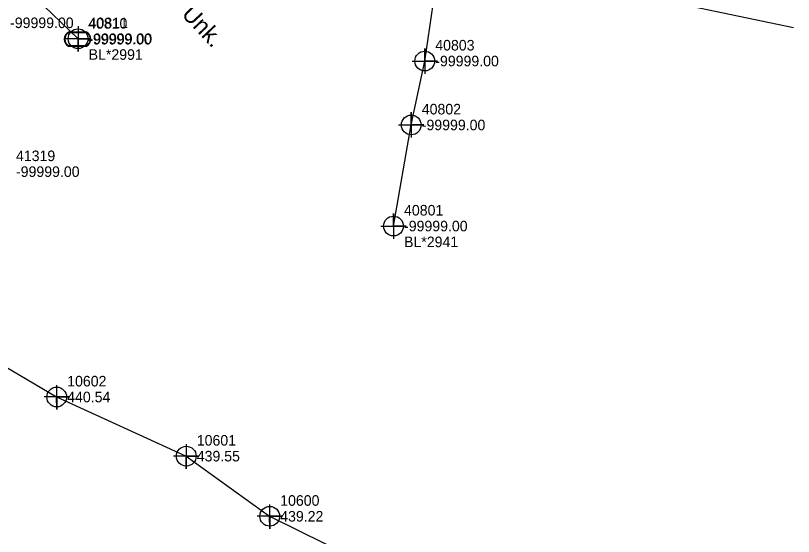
# Model space of a CAD drawing. Extents: x 2083698 to 2094313, y 743246 to 752873.
# Drawn here: x 2091601.9 to 2091786.2, y 744139.8 to 744263.2 of the extents above; entities that cross this region are included whole.
import ezdxf

# ---------------------------------------------------------------- set-up
doc = ezdxf.new("R2010")
doc.units = 0
for name, color, linetype in [('COGO Default Chain', 7, 'Continuous'), ('COGO Default Curve', 7, 'Continuous'), ('COGO Default Point Number', 7, 'Continuous'), ('Default Symbol Cogo Comment', 7, 'Continuous'), ('Exist Guardrail', 7, 'Continuous'), ('Exist Property Line', 7, 'Continuous'), ('Exist Right of Way Easement Line', 7, 'Continuous'), ('Exist Right of Way Line', 7, 'Continuous'), ('Exist Right of Way Line Leader', 7, 'Continuous'), ('Exist Right of Way Line Text', 7, 'Continuous'), ('Exist Right of Way Width CELL', 7, 'Continuous'), ('Exist Utilities Gas UG Line SUE LOS B', 7, 'Continuous'), ('Exist Utilities Other Pole CELL', 7, 'Continuous'), ('Exist Utilities Power Joint Use Telephone Cogo Elevation', 7, 'Continuous'), ('Exist Utilities Power Joint Use Telephone Cogo Number', 7, 'Continuous'), ('Exist Utilities Telephone UG Conduit SUE LOS B', 7, 'Continuous'), ('Exist Utilities TV UG Cable SUE LOS C', 7, 'Continuous'), ('Exist Utilities Water UG Line SUE LOS B', 7, 'Continuous'), ('Exist Utilities Water UG Line SUE LOS C Text', 7, 'Continuous'), ('Old_Level_20', 7, 'Continuous'), ('Scratch_Level_2', 7, 'Continuous')]:
    doc.layers.add(name, color=color, linetype=linetype)

msp = doc.modelspace()

# ---------------------------------------------------------------- linework, layer by layer
at = {"layer": 'COGO Default Curve'}
for points in [[(2091695.86, 744252.45), (2091701.86, 744252.45), (2091698.86, 744252.45), (2091698.86, 744255.45), (2091698.86, 744249.45)], [(2091692.66, 744237.3), (2091698.66, 744237.3), (2091695.66, 744237.3), (2091695.66, 744240.3), (2091695.66, 744234.3)], [(2091688.46, 744213.35), (2091694.46, 744213.35), (2091691.46, 744213.35), (2091691.46, 744216.35), (2091691.46, 744210.35)]]:
    msp.add_lwpolyline(points, dxfattribs=at)
for centre in [(2091698.86, 744252.45), (2091695.66, 744237.3), (2091691.46, 744213.35)]:
    msp.add_circle(centre, 2.34, dxfattribs=at)
at = {"layer": 'COGO Default Point Number'}
msp.add_lwpolyline([(2091616.73, 744260.74), (2091616.73, 744254.74), (2091616.73, 744257.74), (2091619.73, 744257.74), (2091613.73, 744257.74)], dxfattribs=at)
msp.add_circle((2091616.73, 744257.74), 2.34, dxfattribs=at)
at = {"layer": 'Exist Guardrail'}
msp.add_line((2091616.61, 744257.62), (2091616.61, 744257.62), dxfattribs=at)
for points in [[(2091614.57, 744259.33), (2091618.64, 744259.33)], [(2091614.57, 744259.19), (2091618.64, 744259.19)], [(2091618.64, 744256.06), (2091614.54, 744256.06)], [(2091618.64, 744255.93), (2091614.54, 744255.93)]]:
    msp.add_lwpolyline(points, dxfattribs=at)
for centre, radius, start, end in [((2091615.3, 744257.62), 1.86, 113.178, 245.9794), ((2091615.31, 744257.62), 1.73, 115.3009, 243.7824), ((2091617.9, 744257.63), 1.86, 293.6483, 66.3084), ((2091617.91, 744257.62), 1.73, 295.1272, 64.8728)]:
    msp.add_arc(centre, radius, start, end, dxfattribs=at)
at = {"layer": 'Exist Right of Way Line Text'}
for points in [[(2091611.63, 744175.66), (2091611.66, 744169.85), (2091611.65, 744172.85), (2091614.66, 744172.85), (2091608.66, 744172.85)], [(2091642.33, 744161.65), (2091642.36, 744155.83), (2091642.35, 744158.83), (2091645.36, 744158.83), (2091639.36, 744158.83)], [(2091662.11, 744147.39), (2091662.14, 744141.58), (2091662.12, 744144.58), (2091665.14, 744144.58), (2091659.14, 744144.58)]]:
    msp.add_lwpolyline(points, dxfattribs=at)
for centre in [(2091611.66, 744172.85), (2091642.36, 744158.83), (2091662.14, 744144.58)]:
    msp.add_circle(centre, 2.34, dxfattribs=at)
at = {"layer": 'Exist Utilities Gas UG Line SUE LOS B'}
msp.add_lwpolyline([(2091691.46, 744213.35), (2091695.66, 744237.3), (2091698.86, 744252.45), (2091703.26, 744282.01), (2091705.58, 744295.83), (2091707.19, 744318.23), (2091708.17, 744354.23), (2091707.98, 744366.51), (2091708.44, 744376.01)], dxfattribs=at)
at = {"layer": 'Exist Utilities Telephone UG Conduit SUE LOS B'}
msp.add_lwpolyline([(2091279.18, 744292.69), (2091315.02, 744278.76), (2091321.95, 744280.12), (2091332.75, 744276.84), (2091368.39, 744262.43), (2091388.82, 744252.89), (2091414.09, 744244.56), (2091447.81, 744232.66), (2091476.66, 744221.6), (2091494.85, 744211.28), (2091532.15, 744199.88), (2091571.71, 744185.85), (2091572.98, 744186.76), (2091573.83, 744188.71), (2091573.64, 744191.62), (2091574.56, 744194.16), (2091581.59, 744190.58), (2091611.65, 744172.85), (2091642.35, 744158.83), (2091662.12, 744144.58), (2091682.07, 744134.72), (2091715.19, 744120.27), (2091734.08, 744112.32)], dxfattribs=at)
at = {"layer": 'Exist Utilities TV UG Cable SUE LOS C'}
msp.add_lwpolyline([(2091054.67, 744436.34), (2091073.65, 744432.47), (2091178.42, 744410.18), (2091400.3, 744362.19), (2091479.76, 744342.26), (2091533.68, 744324.76), (2091743.8, 744269.35), (2091786.22, 744260.43)], dxfattribs=at)
at = {"layer": 'Exist Utilities Water UG Line SUE LOS B'}
msp.add_line((2091616.73, 744257.74), (2091605.36, 744268.69), dxfattribs=at)

# ---------------------------------------------------------------- texts
at = {"layer": 'COGO Default Chain'}
for p in [(2091701.36, 744251.2), (2091698.16, 744236.05), (2091693.96, 744212.1)]:
    msp.add_text('-99999.00', height=2.5, dxfattribs=at).set_placement(p)
at = {"layer": 'Default Symbol Cogo Comment'}
msp.add_text('-99999.00', height=2.5, dxfattribs=at).set_placement((2091619.11, 744256.38))
at = {"layer": 'Exist Property Line'}
for p in [(2091600.62, 744260.26), (2091619.23, 744256.49)]:
    msp.add_text('-99999.00', height=2.5, dxfattribs=at).set_placement(p)
at = {"layer": 'Exist Right of Way Easement Line'}
msp.add_text('BL*2941', height=2.5, dxfattribs=at).set_placement((2091693.96, 744208.35))
at = {"layer": 'Exist Right of Way Line'}
msp.add_text('40811', height=2.5, dxfattribs=at).set_placement((2091619.23, 744260.24))
at = {"layer": 'Exist Right of Way Line Leader'}
for s, p in [('10602', (2091614.15, 744175.35)), ('10601', (2091644.85, 744161.33)), ('10600', (2091664.62, 744147.08))]:
    msp.add_text(s, height=2.5, dxfattribs=at).set_placement(p)
at = {"layer": 'Exist Right of Way Width CELL'}
msp.add_text('BL*2991', height=2.5, dxfattribs=at).set_placement((2091619.23, 744252.74))
at = {"layer": 'Exist Utilities Other Pole CELL'}
msp.add_text('40810', height=2.5, dxfattribs=at).set_placement((2091619.11, 744260.12))
at = {"layer": 'Exist Utilities Power Joint Use Telephone Cogo Elevation'}
msp.add_text('-99999.00', height=2.5, dxfattribs=at).set_placement((2091602.02, 744224.99))
at = {"layer": 'Exist Utilities Power Joint Use Telephone Cogo Number'}
msp.add_text('41319', height=2.5, dxfattribs=at).set_placement((2091602.02, 744228.74))
at = {"layer": 'Exist Utilities Water UG Line SUE LOS C Text'}
msp.add_text('COR, 8" Unk.', height=4, rotation=313.3425, dxfattribs=at).set_placement((2091626.49, 744278.82))
at = {"layer": 'Old_Level_20'}
for s, p in [('40803', (2091701.36, 744254.95)), ('40802', (2091698.16, 744239.8)), ('40801', (2091693.96, 744215.85))]:
    msp.add_text(s, height=2.5, dxfattribs=at).set_placement(p)
at = {"layer": 'Scratch_Level_2'}
for s, p in [('440.54', (2091614.15, 744171.6)), ('439.55', (2091644.85, 744157.58)), ('439.22', (2091664.62, 744143.33))]:
    msp.add_text(s, height=2.5, dxfattribs=at).set_placement(p)

doc.saveas('drawing.dxf')
